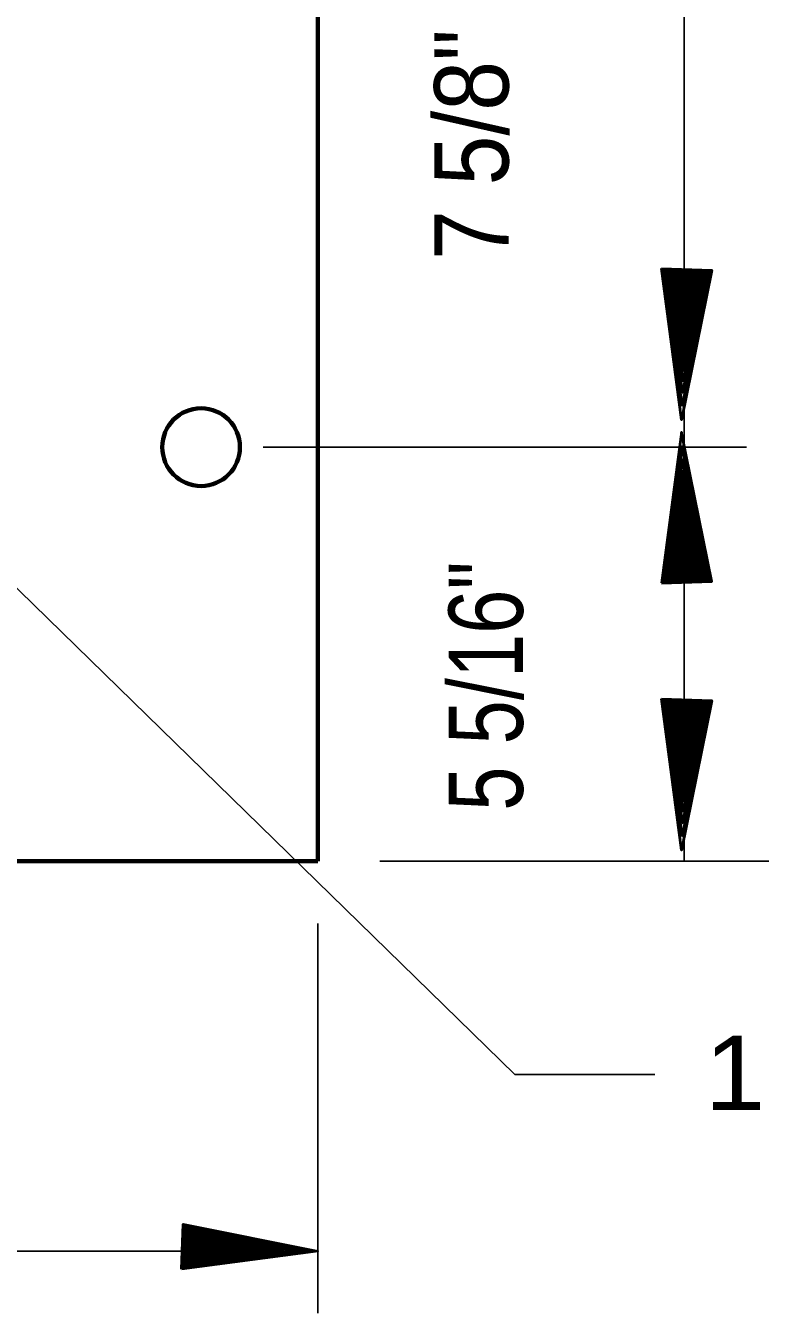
# Model space of a CAD drawing. Extents: x 895.6 to 930.4, y -2278.6 to -2254.7.
# Drawn here: x 902.847 to 904.118, y -2262.172 to -2259.945 of the extents above; entities that cross this region are included whole.
import ezdxf

# ---------------------------------------------------------------- set-up
doc = ezdxf.new("R2010")
doc.units = 0
doc.header["$LTSCALE"] = 0.051
doc.layers.add('1', color=7, linetype='Continuous', lineweight=70)
doc.layers.add('3', color=7, linetype='Continuous', lineweight=40)

msp = doc.modelspace()

# ---------------------------------------------------------------- hatches: boundary and pattern name
at = {"layer": '3'}
for points in [[(903.947, -2260.36558), (904.03367, -2260.3685), (903.9815, -2260.62692), (903.9815, -2260.62692)], [(903.95133, -2260.36683), (904.02933, -2260.36958), (903.98233, -2260.60217), (903.98233, -2260.60217)], [(903.95525, -2260.36808), (904.02533, -2260.37042), (903.98308, -2260.57975), (903.98308, -2260.57975)], [(903.95867, -2260.36908), (904.02175, -2260.37125), (903.98375, -2260.55975), (903.98375, -2260.55975)], [(903.96167, -2260.37), (904.0185, -2260.37192), (903.98433, -2260.54167), (903.98433, -2260.54167)], [(903.96458, -2260.37108), (904.01567, -2260.37267), (903.98483, -2260.52542), (903.98483, -2260.52542)], [(903.96717, -2260.37175), (904.01308, -2260.37325), (903.98533, -2260.51067), (903.98533, -2260.51067)], [(903.96933, -2260.37258), (904.01083, -2260.37383), (903.98583, -2260.49742), (903.98583, -2260.49742)], [(903.97133, -2260.373), (904.00875, -2260.37433), (903.98633, -2260.48567), (903.98633, -2260.48567)], [(903.97333, -2260.37375), (904.007, -2260.37492), (903.98667, -2260.47483), (903.98667, -2260.47483)], [(903.97483, -2260.37417), (904.00517, -2260.37525), (903.98692, -2260.46525), (903.98692, -2260.46525)], [(903.97642, -2260.37467), (904.00358, -2260.37567), (903.98733, -2260.45667), (903.98733, -2260.45667)], [(903.97775, -2260.37508), (904.00225, -2260.37592), (903.98758, -2260.44875), (903.98758, -2260.44875)], [(903.979, -2260.37567), (904.00108, -2260.37617), (903.98775, -2260.44183), (903.98775, -2260.44183)], [(903.98008, -2260.37583), (903.99992, -2260.3765), (903.98792, -2260.43558), (903.98792, -2260.43558)], [(903.98108, -2260.37625), (903.99892, -2260.37667), (903.98825, -2260.42992), (903.98825, -2260.42992)], [(903.982, -2260.37642), (903.99808, -2260.377), (903.98842, -2260.42483), (903.98842, -2260.42483)], [(903.98283, -2260.37658), (903.99725, -2260.37717), (903.98858, -2260.42025), (903.98858, -2260.42025)], [(903.98325, -2260.377), (903.99642, -2260.37725), (903.98858, -2260.41617), (903.98858, -2260.41617)], [(903.98383, -2260.37717), (903.99567, -2260.37758), (903.98867, -2260.4125), (903.98867, -2260.4125)], [(903.98433, -2260.3775), (903.99492, -2260.37792), (903.9885, -2260.40925), (903.9885, -2260.40925)], [(903.98492, -2260.3775), (903.99433, -2260.37792), (903.98867, -2260.40617), (903.98867, -2260.40617)], [(903.98542, -2260.37767), (903.99392, -2260.378), (903.98892, -2260.40342), (903.98892, -2260.40342)], [(903.98583, -2260.37792), (903.99342, -2260.37808), (903.98883, -2260.40108), (903.98883, -2260.40108)], [(903.947, -2260.90975), (904.03367, -2260.90683), (903.9815, -2260.64842), (903.9815, -2260.64842)], [(903.95133, -2260.9085), (904.02933, -2260.90575), (903.98233, -2260.67317), (903.98233, -2260.67317)], [(903.95525, -2260.90725), (904.02533, -2260.90492), (903.98308, -2260.69558), (903.98308, -2260.69558)], [(903.95867, -2260.90625), (904.02175, -2260.90408), (903.98375, -2260.71558), (903.98375, -2260.71558)], [(903.96167, -2260.90533), (904.0185, -2260.90342), (903.98433, -2260.73367), (903.98433, -2260.73367)], [(903.96458, -2260.90425), (904.01567, -2260.90267), (903.98483, -2260.74992), (903.98483, -2260.74992)], [(903.96717, -2260.90358), (904.01308, -2260.90208), (903.98533, -2260.76467), (903.98533, -2260.76467)], [(903.96933, -2260.90275), (904.01083, -2260.9015), (903.98583, -2260.77792), (903.98583, -2260.77792)], [(903.97133, -2260.90233), (904.00875, -2260.901), (903.98633, -2260.78967), (903.98633, -2260.78967)], [(903.97333, -2260.90158), (904.007, -2260.90042), (903.98667, -2260.8005), (903.98667, -2260.8005)], [(903.97483, -2260.90117), (904.00517, -2260.90008), (903.98692, -2260.81008), (903.98692, -2260.81008)], [(903.97642, -2260.90067), (904.00358, -2260.89967), (903.98733, -2260.81867), (903.98733, -2260.81867)], [(903.97775, -2260.90025), (904.00225, -2260.89942), (903.98758, -2260.82658), (903.98758, -2260.82658)], [(903.979, -2260.89967), (904.00108, -2260.89917), (903.98775, -2260.8335), (903.98775, -2260.8335)], [(903.98008, -2260.8995), (903.99992, -2260.89883), (903.98792, -2260.83975), (903.98792, -2260.83975)], [(903.98108, -2260.89908), (903.99892, -2260.89867), (903.98825, -2260.84542), (903.98825, -2260.84542)], [(903.982, -2260.89892), (903.99808, -2260.89833), (903.98842, -2260.8505), (903.98842, -2260.8505)], [(903.98283, -2260.89875), (903.99725, -2260.89817), (903.98858, -2260.85508), (903.98858, -2260.85508)], [(903.98325, -2260.89833), (903.99642, -2260.89808), (903.98858, -2260.85917), (903.98858, -2260.85917)], [(903.98383, -2260.89817), (903.99567, -2260.89775), (903.98867, -2260.86283), (903.98867, -2260.86283)], [(903.98433, -2260.89783), (903.99492, -2260.89742), (903.9885, -2260.86608), (903.9885, -2260.86608)], [(903.98492, -2260.89783), (903.99433, -2260.89742), (903.98867, -2260.86917), (903.98867, -2260.86917)], [(903.98542, -2260.89767), (903.99392, -2260.89733), (903.98892, -2260.87192), (903.98892, -2260.87192)], [(903.98583, -2260.89742), (903.99342, -2260.89725), (903.98883, -2260.87425), (903.98883, -2260.87425)], [(903.947, -2261.10975), (904.03367, -2261.11267), (903.9815, -2261.37108), (903.9815, -2261.37108)], [(903.95133, -2261.111), (904.02933, -2261.11375), (903.98233, -2261.34633), (903.98233, -2261.34633)], [(903.95525, -2261.11225), (904.02533, -2261.11458), (903.98308, -2261.32392), (903.98308, -2261.32392)], [(903.95867, -2261.11325), (904.02175, -2261.11542), (903.98375, -2261.30392), (903.98375, -2261.30392)], [(903.96167, -2261.11417), (904.0185, -2261.11608), (903.98433, -2261.28583), (903.98433, -2261.28583)], [(903.96458, -2261.11525), (904.01567, -2261.11683), (903.98483, -2261.26958), (903.98483, -2261.26958)], [(903.96717, -2261.11592), (904.01308, -2261.11742), (903.98533, -2261.25483), (903.98533, -2261.25483)], [(903.96933, -2261.11675), (904.01083, -2261.118), (903.98583, -2261.24158), (903.98583, -2261.24158)], [(903.97133, -2261.11717), (904.00875, -2261.1185), (903.98633, -2261.22983), (903.98633, -2261.22983)], [(903.97333, -2261.11792), (904.007, -2261.11908), (903.98667, -2261.219), (903.98667, -2261.219)], [(903.97483, -2261.11833), (904.00517, -2261.11942), (903.98692, -2261.20942), (903.98692, -2261.20942)], [(903.97642, -2261.11883), (904.00358, -2261.11983), (903.98733, -2261.20083), (903.98733, -2261.20083)], [(903.97775, -2261.11925), (904.00225, -2261.12008), (903.98758, -2261.19292), (903.98758, -2261.19292)], [(903.979, -2261.11983), (904.00108, -2261.12033), (903.98775, -2261.186), (903.98775, -2261.186)], [(903.98008, -2261.12), (903.99992, -2261.12067), (903.98792, -2261.17975), (903.98792, -2261.17975)], [(903.98108, -2261.12042), (903.99892, -2261.12083), (903.98825, -2261.17408), (903.98825, -2261.17408)], [(903.982, -2261.12058), (903.99808, -2261.12117), (903.98842, -2261.169), (903.98842, -2261.169)], [(903.98283, -2261.12075), (903.99725, -2261.12133), (903.98858, -2261.16442), (903.98858, -2261.16442)], [(903.98325, -2261.12117), (903.99642, -2261.12142), (903.98858, -2261.16033), (903.98858, -2261.16033)], [(903.98383, -2261.12133), (903.99567, -2261.12175), (903.98867, -2261.15667), (903.98867, -2261.15667)], [(903.98433, -2261.12167), (903.99492, -2261.12208), (903.9885, -2261.15342), (903.9885, -2261.15342)], [(903.98492, -2261.12167), (903.99433, -2261.12208), (903.98867, -2261.15033), (903.98867, -2261.15033)], [(903.98542, -2261.12183), (903.99392, -2261.12217), (903.98892, -2261.14758), (903.98892, -2261.14758)], [(903.98583, -2261.12208), (903.99342, -2261.12225), (903.98883, -2261.14525), (903.98883, -2261.14525)], [(903.11675, -2262.09608), (903.11942, -2262.01808), (903.35208, -2262.065), (903.35208, -2262.065)], [(903.118, -2262.09217), (903.12033, -2262.022), (903.32967, -2262.06417), (903.32967, -2262.06417)], [(903.119, -2262.08867), (903.12117, -2262.02558), (903.30958, -2262.06358), (903.30958, -2262.06358)], [(903.12, -2262.08558), (903.12192, -2262.02883), (903.2915, -2262.063), (903.2915, -2262.063)], [(903.12075, -2262.08292), (903.12258, -2262.03175), (903.27525, -2262.0625), (903.27525, -2262.0625)], [(903.12175, -2262.08025), (903.12325, -2262.03425), (903.26058, -2262.062), (903.26058, -2262.062)], [(903.12233, -2262.07792), (903.12367, -2262.0365), (903.24742, -2262.0615), (903.24742, -2262.0615)], [(903.12308, -2262.076), (903.12417, -2262.03867), (903.23542, -2262.06117), (903.23542, -2262.06117)], [(903.12342, -2262.07417), (903.12475, -2262.0405), (903.22483, -2262.06067), (903.22483, -2262.06067)], [(903.12408, -2262.07242), (903.12517, -2262.04208), (903.21517, -2262.06042), (903.21517, -2262.06042)], [(903.12458, -2262.07092), (903.1255, -2262.04375), (903.2065, -2262.06008), (903.2065, -2262.06008)], [(903.12492, -2262.0695), (903.12583, -2262.04517), (903.19875, -2262.05975), (903.19875, -2262.05975)], [(903.12542, -2262.06842), (903.12608, -2262.04633), (903.19158, -2262.05958), (903.19158, -2262.05958)], [(903.12583, -2262.06725), (903.12633, -2262.04742), (903.1855, -2262.05942), (903.1855, -2262.05942)], [(903.12608, -2262.06633), (903.12667, -2262.04842), (903.17975, -2262.05925), (903.17975, -2262.05925)], [(903.12633, -2262.06542), (903.12675, -2262.04925), (903.17467, -2262.05892), (903.17467, -2262.05892)], [(903.12658, -2262.06458), (903.12708, -2262.05), (903.17008, -2262.05875), (903.17008, -2262.05875)], [(903.12675, -2262.06383), (903.12717, -2262.05083), (903.166, -2262.05867), (903.166, -2262.05867)], [(903.12708, -2262.06342), (903.12733, -2262.05158), (903.16233, -2262.05867), (903.16233, -2262.05867)], [(903.12725, -2262.06283), (903.12758, -2262.05225), (903.15908, -2262.05858), (903.15908, -2262.05858)], [(903.1275, -2262.0625), (903.12783, -2262.05292), (903.15608, -2262.05875), (903.15608, -2262.05875)], [(903.1275, -2262.06192), (903.12783, -2262.05342), (903.15333, -2262.05858), (903.15333, -2262.05858)], [(903.12767, -2262.06142), (903.128, -2262.05383), (903.15092, -2262.05833), (903.15092, -2262.05833)], [(903.12783, -2262.06117), (903.12808, -2262.05433), (903.14875, -2262.05842), (903.14875, -2262.05842)]]:
    msp.add_hatch(color=256, dxfattribs=at).paths.add_polyline_path(points)

# ---------------------------------------------------------------- linework, layer by layer
at = {"layer": '1', "lineweight": 25}
for p, q in [((903.98608, -2260.29758), (903.98608, -2259.65142)), ((903.98608, -2260.67433), (903.98608, -2260.02817)), ((903.25775, -2260.67433), (904.0935, -2260.67433)), ((903.98608, -2261.39058), (903.98608, -2260.67433)), ((903.45942, -2261.39058), (904.738, -2261.39058)), ((903.35208, -2261.498), (903.35208, -2262.17225)), ((903.35208, -2262.065), (901.87267, -2262.065))]:
    msp.add_line(p, q, dxfattribs=at)
at = {"layer": '1'}
msp.add_line((901.87267, -2261.39058), (903.35208, -2261.39058), dxfattribs=at)
at = {"layer": '1', "lineweight": 13}
msp.add_line((903.45942, -2261.39058), (904.0935, -2261.39058), dxfattribs=at)
at = {"layer": '1'}
msp.add_lwpolyline([(901.87267, -2258.93683), (903.35208, -2258.93683), (903.35208, -2261.39058)], dxfattribs=at)
at = {"layer": '1', "lineweight": 25}
msp.add_lwpolyline([(903.93533, -2261.75933), (903.69333, -2261.75933), (902.12517, -2260.229), (902.2195, -2260.3485), (902.24942, -2260.31692), (902.12517, -2260.229)], dxfattribs=at)
at = {"layer": '1'}
msp.add_circle((903.15042, -2260.67431), 0.06722, dxfattribs=at)
at = {"layer": '3'}
for points in [[(903.947, -2260.36558), (904.03367, -2260.3685), (903.9815, -2260.62692), (903.9815, -2260.62692)], [(903.95133, -2260.36683), (904.02933, -2260.36958), (903.98233, -2260.60217), (903.98233, -2260.60217)], [(903.95525, -2260.36808), (904.02533, -2260.37042), (903.98308, -2260.57975), (903.98308, -2260.57975)], [(903.95867, -2260.36908), (904.02175, -2260.37125), (903.98375, -2260.55975), (903.98375, -2260.55975)], [(903.96167, -2260.37), (904.0185, -2260.37192), (903.98433, -2260.54167), (903.98433, -2260.54167)], [(903.96458, -2260.37108), (904.01567, -2260.37267), (903.98483, -2260.52542), (903.98483, -2260.52542)], [(903.96717, -2260.37175), (904.01308, -2260.37325), (903.98533, -2260.51067), (903.98533, -2260.51067)], [(903.96933, -2260.37258), (904.01083, -2260.37383), (903.98583, -2260.49742), (903.98583, -2260.49742)], [(903.97133, -2260.373), (904.00875, -2260.37433), (903.98633, -2260.48567), (903.98633, -2260.48567)], [(903.97333, -2260.37375), (904.007, -2260.37492), (903.98667, -2260.47483), (903.98667, -2260.47483)], [(903.97483, -2260.37417), (904.00517, -2260.37525), (903.98692, -2260.46525), (903.98692, -2260.46525)], [(903.97642, -2260.37467), (904.00358, -2260.37567), (903.98733, -2260.45667), (903.98733, -2260.45667)], [(903.97775, -2260.37508), (904.00225, -2260.37592), (903.98758, -2260.44875), (903.98758, -2260.44875)], [(903.979, -2260.37567), (904.00108, -2260.37617), (903.98775, -2260.44183), (903.98775, -2260.44183)], [(903.98008, -2260.37583), (903.99992, -2260.3765), (903.98792, -2260.43558), (903.98792, -2260.43558)], [(903.98108, -2260.37625), (903.99892, -2260.37667), (903.98825, -2260.42992), (903.98825, -2260.42992)], [(903.982, -2260.37642), (903.99808, -2260.377), (903.98842, -2260.42483), (903.98842, -2260.42483)], [(903.98283, -2260.37658), (903.99725, -2260.37717), (903.98858, -2260.42025), (903.98858, -2260.42025)], [(903.98325, -2260.377), (903.99642, -2260.37725), (903.98858, -2260.41617), (903.98858, -2260.41617)], [(903.98383, -2260.37717), (903.99567, -2260.37758), (903.98867, -2260.4125), (903.98867, -2260.4125)], [(903.98433, -2260.3775), (903.99492, -2260.37792), (903.9885, -2260.40925), (903.9885, -2260.40925)], [(903.98492, -2260.3775), (903.99433, -2260.37792), (903.98867, -2260.40617), (903.98867, -2260.40617)], [(903.98542, -2260.37767), (903.99392, -2260.378), (903.98892, -2260.40342), (903.98892, -2260.40342)], [(903.98583, -2260.37792), (903.99342, -2260.37808), (903.98883, -2260.40108), (903.98883, -2260.40108)], [(903.947, -2260.90975), (904.03367, -2260.90683), (903.9815, -2260.64842), (903.9815, -2260.64842)], [(903.95133, -2260.9085), (904.02933, -2260.90575), (903.98233, -2260.67317), (903.98233, -2260.67317)], [(903.95525, -2260.90725), (904.02533, -2260.90492), (903.98308, -2260.69558), (903.98308, -2260.69558)], [(903.95867, -2260.90625), (904.02175, -2260.90408), (903.98375, -2260.71558), (903.98375, -2260.71558)], [(903.96167, -2260.90533), (904.0185, -2260.90342), (903.98433, -2260.73367), (903.98433, -2260.73367)], [(903.96458, -2260.90425), (904.01567, -2260.90267), (903.98483, -2260.74992), (903.98483, -2260.74992)], [(903.96717, -2260.90358), (904.01308, -2260.90208), (903.98533, -2260.76467), (903.98533, -2260.76467)], [(903.96933, -2260.90275), (904.01083, -2260.9015), (903.98583, -2260.77792), (903.98583, -2260.77792)], [(903.97133, -2260.90233), (904.00875, -2260.901), (903.98633, -2260.78967), (903.98633, -2260.78967)], [(903.97333, -2260.90158), (904.007, -2260.90042), (903.98667, -2260.8005), (903.98667, -2260.8005)], [(903.97483, -2260.90117), (904.00517, -2260.90008), (903.98692, -2260.81008), (903.98692, -2260.81008)], [(903.97642, -2260.90067), (904.00358, -2260.89967), (903.98733, -2260.81867), (903.98733, -2260.81867)], [(903.97775, -2260.90025), (904.00225, -2260.89942), (903.98758, -2260.82658), (903.98758, -2260.82658)], [(903.979, -2260.89967), (904.00108, -2260.89917), (903.98775, -2260.8335), (903.98775, -2260.8335)], [(903.98008, -2260.8995), (903.99992, -2260.89883), (903.98792, -2260.83975), (903.98792, -2260.83975)], [(903.98108, -2260.89908), (903.99892, -2260.89867), (903.98825, -2260.84542), (903.98825, -2260.84542)], [(903.982, -2260.89892), (903.99808, -2260.89833), (903.98842, -2260.8505), (903.98842, -2260.8505)], [(903.98283, -2260.89875), (903.99725, -2260.89817), (903.98858, -2260.85508), (903.98858, -2260.85508)], [(903.98325, -2260.89833), (903.99642, -2260.89808), (903.98858, -2260.85917), (903.98858, -2260.85917)], [(903.98383, -2260.89817), (903.99567, -2260.89775), (903.98867, -2260.86283), (903.98867, -2260.86283)], [(903.98433, -2260.89783), (903.99492, -2260.89742), (903.9885, -2260.86608), (903.9885, -2260.86608)], [(903.98492, -2260.89783), (903.99433, -2260.89742), (903.98867, -2260.86917), (903.98867, -2260.86917)], [(903.98542, -2260.89767), (903.99392, -2260.89733), (903.98892, -2260.87192), (903.98892, -2260.87192)], [(903.98583, -2260.89742), (903.99342, -2260.89725), (903.98883, -2260.87425), (903.98883, -2260.87425)], [(903.947, -2261.10975), (904.03367, -2261.11267), (903.9815, -2261.37108), (903.9815, -2261.37108)], [(903.95133, -2261.111), (904.02933, -2261.11375), (903.98233, -2261.34633), (903.98233, -2261.34633)], [(903.95525, -2261.11225), (904.02533, -2261.11458), (903.98308, -2261.32392), (903.98308, -2261.32392)], [(903.95867, -2261.11325), (904.02175, -2261.11542), (903.98375, -2261.30392), (903.98375, -2261.30392)], [(903.96167, -2261.11417), (904.0185, -2261.11608), (903.98433, -2261.28583), (903.98433, -2261.28583)], [(903.96458, -2261.11525), (904.01567, -2261.11683), (903.98483, -2261.26958), (903.98483, -2261.26958)], [(903.96717, -2261.11592), (904.01308, -2261.11742), (903.98533, -2261.25483), (903.98533, -2261.25483)], [(903.96933, -2261.11675), (904.01083, -2261.118), (903.98583, -2261.24158), (903.98583, -2261.24158)], [(903.97133, -2261.11717), (904.00875, -2261.1185), (903.98633, -2261.22983), (903.98633, -2261.22983)], [(903.97333, -2261.11792), (904.007, -2261.11908), (903.98667, -2261.219), (903.98667, -2261.219)], [(903.97483, -2261.11833), (904.00517, -2261.11942), (903.98692, -2261.20942), (903.98692, -2261.20942)], [(903.97642, -2261.11883), (904.00358, -2261.11983), (903.98733, -2261.20083), (903.98733, -2261.20083)], [(903.97775, -2261.11925), (904.00225, -2261.12008), (903.98758, -2261.19292), (903.98758, -2261.19292)], [(903.979, -2261.11983), (904.00108, -2261.12033), (903.98775, -2261.186), (903.98775, -2261.186)], [(903.98008, -2261.12), (903.99992, -2261.12067), (903.98792, -2261.17975), (903.98792, -2261.17975)], [(903.98108, -2261.12042), (903.99892, -2261.12083), (903.98825, -2261.17408), (903.98825, -2261.17408)], [(903.982, -2261.12058), (903.99808, -2261.12117), (903.98842, -2261.169), (903.98842, -2261.169)], [(903.98283, -2261.12075), (903.99725, -2261.12133), (903.98858, -2261.16442), (903.98858, -2261.16442)], [(903.98325, -2261.12117), (903.99642, -2261.12142), (903.98858, -2261.16033), (903.98858, -2261.16033)], [(903.98383, -2261.12133), (903.99567, -2261.12175), (903.98867, -2261.15667), (903.98867, -2261.15667)], [(903.98433, -2261.12167), (903.99492, -2261.12208), (903.9885, -2261.15342), (903.9885, -2261.15342)], [(903.98492, -2261.12167), (903.99433, -2261.12208), (903.98867, -2261.15033), (903.98867, -2261.15033)], [(903.98542, -2261.12183), (903.99392, -2261.12217), (903.98892, -2261.14758), (903.98892, -2261.14758)], [(903.98583, -2261.12208), (903.99342, -2261.12225), (903.98883, -2261.14525), (903.98883, -2261.14525)], [(903.11675, -2262.09608), (903.11942, -2262.01808), (903.35208, -2262.065), (903.35208, -2262.065)], [(903.118, -2262.09217), (903.12033, -2262.022), (903.32967, -2262.06417), (903.32967, -2262.06417)], [(903.119, -2262.08867), (903.12117, -2262.02558), (903.30958, -2262.06358), (903.30958, -2262.06358)], [(903.12, -2262.08558), (903.12192, -2262.02883), (903.2915, -2262.063), (903.2915, -2262.063)], [(903.12075, -2262.08292), (903.12258, -2262.03175), (903.27525, -2262.0625), (903.27525, -2262.0625)], [(903.12175, -2262.08025), (903.12325, -2262.03425), (903.26058, -2262.062), (903.26058, -2262.062)], [(903.12233, -2262.07792), (903.12367, -2262.0365), (903.24742, -2262.0615), (903.24742, -2262.0615)], [(903.12308, -2262.076), (903.12417, -2262.03867), (903.23542, -2262.06117), (903.23542, -2262.06117)], [(903.12342, -2262.07417), (903.12475, -2262.0405), (903.22483, -2262.06067), (903.22483, -2262.06067)], [(903.12408, -2262.07242), (903.12517, -2262.04208), (903.21517, -2262.06042), (903.21517, -2262.06042)], [(903.12458, -2262.07092), (903.1255, -2262.04375), (903.2065, -2262.06008), (903.2065, -2262.06008)], [(903.12492, -2262.0695), (903.12583, -2262.04517), (903.19875, -2262.05975), (903.19875, -2262.05975)], [(903.12542, -2262.06842), (903.12608, -2262.04633), (903.19158, -2262.05958), (903.19158, -2262.05958)], [(903.12583, -2262.06725), (903.12633, -2262.04742), (903.1855, -2262.05942), (903.1855, -2262.05942)], [(903.12608, -2262.06633), (903.12667, -2262.04842), (903.17975, -2262.05925), (903.17975, -2262.05925)], [(903.12633, -2262.06542), (903.12675, -2262.04925), (903.17467, -2262.05892), (903.17467, -2262.05892)], [(903.12658, -2262.06458), (903.12708, -2262.05), (903.17008, -2262.05875), (903.17008, -2262.05875)], [(903.12675, -2262.06383), (903.12717, -2262.05083), (903.166, -2262.05867), (903.166, -2262.05867)], [(903.12708, -2262.06342), (903.12733, -2262.05158), (903.16233, -2262.05867), (903.16233, -2262.05867)], [(903.12725, -2262.06283), (903.12758, -2262.05225), (903.15908, -2262.05858), (903.15908, -2262.05858)], [(903.1275, -2262.0625), (903.12783, -2262.05292), (903.15608, -2262.05875), (903.15608, -2262.05875)], [(903.1275, -2262.06192), (903.12783, -2262.05342), (903.15333, -2262.05858), (903.15333, -2262.05858)], [(903.12767, -2262.06142), (903.128, -2262.05383), (903.15092, -2262.05833), (903.15092, -2262.05833)], [(903.12783, -2262.06117), (903.12808, -2262.05433), (903.14875, -2262.05842), (903.14875, -2262.05842)]]:
    msp.add_lwpolyline(points, close=True, dxfattribs=at)

# ---------------------------------------------------------------- texts
at = {"layer": '1'}
for s, width, p in [('7 5/8"', 0.9, (903.68217, -2260.35067)), ('5 5/16"', 0.8, (903.707, -2261.30317))]:
    msp.add_text(s, height=0.1286, rotation=90, dxfattribs=dict(at, width=width)).set_placement(p)
at = {"layer": '1', "width": 1.1}
msp.add_text('1"   Holes (typ)', height=0.1286, dxfattribs=at).set_placement((904.02117, -2261.82075))

doc.saveas('drawing.dxf')
